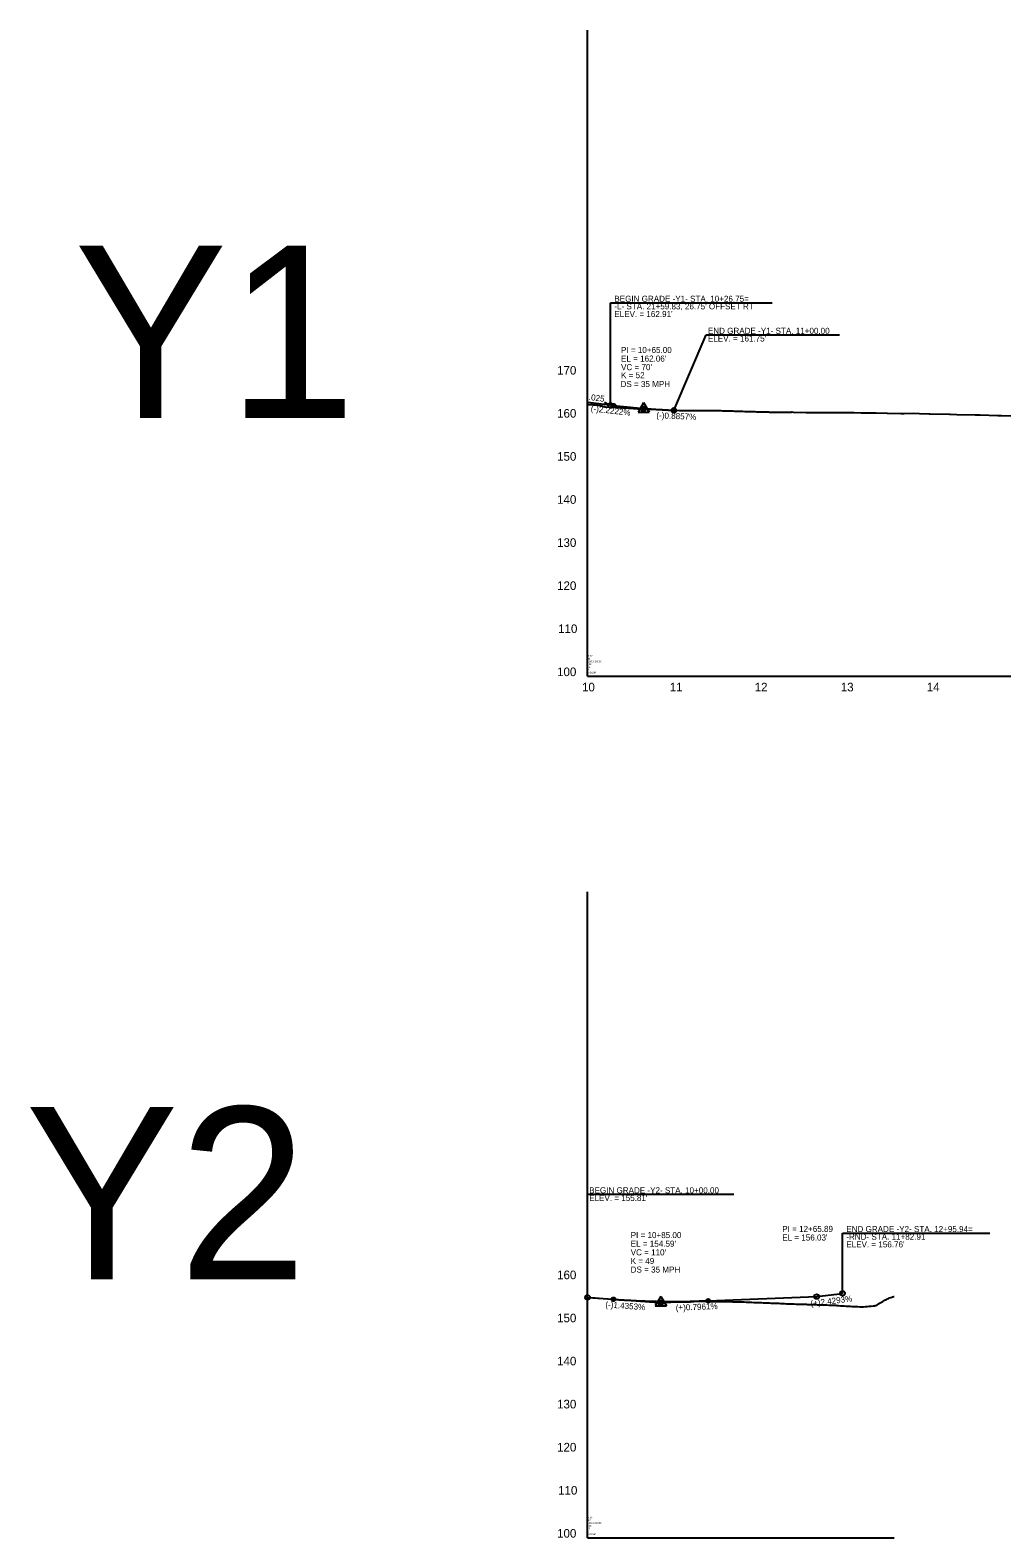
# Model space of a CAD drawing. Extents: x 1778432 to 1784301, y 601022 to 621789.
# Drawn here: x 1779496 to 1780624, y 617039 to 618789 of the extents above; entities that cross this region are included whole.
import ezdxf

# ---------------------------------------------------------------- set-up
doc = ezdxf.new("R2010")
doc.units = 0
for name, color, linetype in [('Exist Profile Cell', 7, 'Continuous'), ('Exist Vertical Profile Ground Line', 7, 'Continuous'), ('Exist Vertical Profile Horizontal Axis Label Major', 7, 'Continuous'), ('Exist Vertical Profile Vertical Axis Label', 7, 'Continuous'), ('Prop PFL Text', 7, 'Continuous'), ('Prop PFL VPI Symbol CELL', 7, 'Continuous'), ('Prop Vertical Profile Curve Label', 7, 'Continuous'), ('Prop Vertical Profile Grade', 7, 'Continuous'), ('Prop Vertical Profile Grade Label', 7, 'Continuous'), ('Prop VPI Label', 7, 'Continuous'), ('Scratch_Level_1', 7, 'Continuous')]:
    doc.layers.add(name, color=color, linetype=linetype)

msp = doc.modelspace()

# ---------------------------------------------------------------- linework, layer by layer
at = {"layer": 'Exist Profile Cell'}
for p, q in [((1780143, 618039.2), (1780143, 618789.2)), ((1780143, 618039.2), (1781686.3, 618039.2)), ((1780143, 618039.2), (1780143, 618039.2)), ((1780143, 617039.2), (1780143, 617789.2)), ((1780143, 617039.2), (1780498.9, 617039.2)), ((1780143, 617039.2), (1780143, 617039.2))]:
    msp.add_line(p, q, dxfattribs=at)
at = {"layer": 'Exist Vertical Profile Ground Line'}
for points in [[(1780143, 618354.7), (1780144.8, 618354.6), (1780147.3, 618354.6), (1780148.2, 618354.5), (1780149.8, 618354.4), (1780152.3, 618354.2), (1780154.4, 618353.9), (1780154.8, 618353.8), (1780156.7, 618353.7), (1780157.3, 618353.6), (1780157.7, 618353.5), (1780158.6, 618353.3), (1780159.2, 618353.1), (1780159.8, 618353), (1780161.5, 618352.5), (1780162.3, 618352.3), (1780163.1, 618352), (1780163.9, 618351.9), (1780190.9, 618350.4), (1780191.8, 618350.3), (1780196.1, 618350.1), (1780200.9, 618349.8), (1780225.9, 618348.8), (1780231.3, 618348.4), (1780249.6, 618347.7), (1780253.9, 618347.6), (1780268, 618347.6), (1780270, 618347.6), (1780272, 618347.6), (1780274, 618347.6), (1780275.9, 618347.6), (1780277.9, 618347.6), (1780280.1, 618347.6), (1780281, 618347.6), (1780281.9, 618347.6), (1780283.8, 618347.6), (1780285.8, 618347.6), (1780287.8, 618347.6), (1780289.8, 618347.6), (1780291.7, 618347.6), (1780292.2, 618347.6), (1780293.7, 618347.6), (1780295.7, 618347.6), (1780297.7, 618347.6), (1780299.6, 618347.5), (1780301.8, 618347.5), (1780303.6, 618347.5), (1780305.5, 618347.4), (1780307.5, 618347.3), (1780309.5, 618347.2), (1780311.5, 618347.2), (1780313.4, 618347.1), (1780315.4, 618347), (1780317.4, 618347), (1780319.4, 618346.9), (1780321.3, 618346.8), (1780323.3, 618346.8), (1780325.3, 618346.7), (1780327.3, 618346.7), (1780329.5, 618346.6), (1780331.2, 618346.6), (1780331.8, 618346.5), (1780333.2, 618346.5), (1780335.2, 618346.4), (1780337.2, 618346.4), (1780339.1, 618346.3), (1780341.1, 618346.3), (1780343, 618346.2), (1780345, 618346.2), (1780347, 618346.1), (1780349, 618346.1), (1780350.9, 618346), (1780352.9, 618346), (1780354, 618345.9), (1780354.4, 618345.9), (1780354.9, 618345.9), (1780356.9, 618345.9), (1780358.8, 618345.9), (1780360.8, 618345.9), (1780362.8, 618345.8), (1780364.8, 618345.8), (1780366.7, 618345.8), (1780368.7, 618345.8), (1780369.3, 618345.8), (1780370.7, 618345.7), (1780372.7, 618345.7), (1780373, 618345.7), (1780374.6, 618345.7), (1780376.6, 618345.7), (1780378.2, 618345.6), (1780379.3, 618345.9), (1780380, 618346), (1780381.4, 618345.6), (1780381.9, 618345.6), (1780396.7, 618345.5), (1780397.7, 618345.5), (1780401.4, 618345.5), (1780410.7, 618345.4), (1780416.1, 618345.4), (1780417.5, 618345.4), (1780418.1, 618345.4)], [(1780418.1, 618345.4), (1780432, 618345.4), (1780432.5, 618345.4), (1780433.7, 618345.4), (1780452.3, 618345.3), (1780460.6, 618345.1), (1780463.7, 618345.1), (1780467.1, 618345.1), (1780478, 618344.9), (1780490.5, 618344.8), (1780491, 618344.8), (1780506.4, 618344.4), (1780509.6, 618344.4), (1780510.4, 618344.4), (1780521.1, 618344.5), (1780528.3, 618344.4), (1780539.3, 618343.8), (1780540.7, 618343.7), (1780562.8, 618343.3), (1780563.8, 618343.3), (1780571.6, 618343.1), (1780592.6, 618342.6), (1780593.5, 618342.6), (1780598, 618342.5), (1780598.5, 618342.5), (1780619, 618342.1), (1780619.7, 618342.1), (1780623.1, 618342), (1780642, 618341.6)], [(1780143, 617318.2), (1780151.6, 617317.6), (1780170.7, 617316.2), (1780171.1, 617316.2), (1780196.9, 617314.5), (1780197.4, 617314.5), (1780208.3, 617313.8), (1780210.5, 617313.7), (1780212.7, 617313.6), (1780215, 617313.4), (1780217.2, 617313.3), (1780219.4, 617313.1), (1780221.7, 617313), (1780223.9, 617312.9), (1780226.1, 617312.7), (1780227.2, 617312.7), (1780228.4, 617312.7), (1780230.7, 617312.8), (1780232.8, 617312.8), (1780235.1, 617312.8), (1780237.3, 617312.9), (1780239.1, 617312.9), (1780239.6, 617312.9), (1780241.8, 617313), (1780244, 617313), (1780246.3, 617313), (1780248.5, 617313.1), (1780250.7, 617313.1), (1780253, 617313.1), (1780255.2, 617313.2), (1780257.4, 617313.2), (1780259.7, 617313.2), (1780261.9, 617313.3), (1780262.4, 617313.3), (1780264.2, 617313.4), (1780266.4, 617313.6), (1780268.6, 617313.8), (1780269.5, 617313.9), (1780270.9, 617313.9), (1780273.1, 617313.8), (1780275.3, 617313.8), (1780277.6, 617313.8), (1780279.8, 617313.8), (1780282, 617313.8), (1780282.8, 617313.7), (1780284.3, 617313.7), (1780286.5, 617313.7), (1780288.7, 617313.6), (1780291, 617313.6), (1780291.6, 617313.6), (1780293.2, 617313.6), (1780295.5, 617313.5), (1780297.7, 617313.5), (1780299.9, 617313.5), (1780302.2, 617313.5), (1780304.4, 617313.4), (1780305.1, 617313.4), (1780306.6, 617313.4), (1780308.9, 617313.4), (1780311.1, 617313.3), (1780313.3, 617313.3), (1780315.6, 617313.2), (1780317.8, 617313.2), (1780320.1, 617313.1), (1780322.3, 617313.1), (1780324.5, 617313), (1780326.8, 617312.9), (1780329, 617312.8), (1780331.2, 617312.7), (1780333.5, 617312.6), (1780335.7, 617312.5), (1780337.9, 617312.4), (1780338.4, 617312.4), (1780340.2, 617312.4), (1780342.4, 617312.3), (1780344.6, 617312.2), (1780346.9, 617312.1), (1780349.1, 617312), (1780351.4, 617311.9), (1780353.6, 617311.8), (1780355.8, 617311.7), (1780358.1, 617311.6), (1780360.3, 617311.6), (1780362.5, 617311.5), (1780364.8, 617311.4), (1780367, 617311.3), (1780369.2, 617311.2), (1780370.5, 617311.2), (1780371.5, 617311.1), (1780373.7, 617311), (1780375.9, 617310.9), (1780376.5, 617310.9), (1780378.2, 617310.9), (1780380.4, 617310.8), (1780382.7, 617310.7), (1780384.9, 617310.6), (1780387.1, 617310.6), (1780389.4, 617310.5), (1780391.6, 617310.4), (1780393.8, 617310.4), (1780396.1, 617310.3), (1780397, 617310.3), (1780398.3, 617310.2), (1780400.5, 617310.1), (1780402.8, 617310), (1780405, 617310), (1780406.5, 617309.9), (1780407.3, 617309.9), (1780409.5, 617309.8), (1780411.7, 617309.7), (1780414, 617309.7), (1780416.2, 617309.6), (1780418.4, 617309.5), (1780420.7, 617309.5), (1780422.9, 617309.4), (1780425.1, 617309.3), (1780425.9, 617309.3), (1780427.4, 617309.3), (1780429.6, 617309.1), (1780431.4, 617309.1), (1780431.8, 617309), (1780434.1, 617308.8), (1780436.3, 617308.6), (1780438.6, 617308.4), (1780439.3, 617308.4), (1780440.8, 617308.3), (1780443, 617308.2), (1780445.3, 617308.1), (1780447.5, 617308), (1780449.7, 617307.9), (1780452, 617307.8), (1780454.2, 617307.7), (1780455.8, 617307.6), (1780456.4, 617307.6), (1780458.7, 617307.5), (1780460.9, 617307.4), (1780461.6, 617307.3), (1780463.1, 617307.5), (1780465.4, 617307.6), (1780467.6, 617307.8), (1780469.9, 617308), (1780472.1, 617308.2), (1780474.3, 617308.4), (1780475.1, 617308.4), (1780476.1, 617308.6), (1780476.6, 617308.7), (1780477.6, 617308.9), (1780478.9, 617309.8), (1780479.4, 617310.2), (1780479.8, 617310.4), (1780480.7, 617311), (1780481, 617311.2), (1780482.3, 617311.9), (1780483.3, 617312.5), (1780484.8, 617313.3), (1780485.5, 617313.7), (1780485.9, 617313.9), (1780487.3, 617314.6), (1780487.7, 617314.9), (1780488.6, 617315.3), (1780490, 617315.9), (1780491.1, 617316.5), (1780492.3, 617317.1), (1780493.5, 617317.6), (1780494.7, 617318.1), (1780496, 617318.5), (1780496.7, 617318.8), (1780497.2, 617319), (1780498.5, 617319.3), (1780498.9, 617319.5)], [(1780396.1, 617310.3), (1780397, 617310.3), (1780398.3, 617310.2), (1780400.5, 617310.1), (1780402.8, 617310), (1780405, 617310), (1780406.5, 617309.9), (1780407.3, 617309.9), (1780409.5, 617309.8), (1780411.7, 617309.7), (1780414, 617309.7), (1780416.2, 617309.6), (1780418.4, 617309.5), (1780420.7, 617309.5), (1780422.9, 617309.4), (1780425.1, 617309.3), (1780425.9, 617309.3), (1780427.4, 617309.3), (1780429.6, 617309.1), (1780431.4, 617309.1), (1780431.8, 617309), (1780434.1, 617308.8), (1780436.3, 617308.6), (1780438.6, 617308.4), (1780439.3, 617308.4), (1780440.8, 617308.3), (1780443, 617308.2), (1780445.3, 617308.1), (1780447.5, 617308), (1780449.7, 617307.9), (1780452, 617307.8), (1780454.2, 617307.7), (1780455.8, 617307.6), (1780456.4, 617307.6), (1780458.7, 617307.5), (1780460.9, 617307.4), (1780461.6, 617307.3), (1780463.1, 617307.5), (1780465.4, 617307.6), (1780467.6, 617307.8), (1780469.9, 617308), (1780472.1, 617308.2), (1780474.3, 617308.4), (1780475.1, 617308.4), (1780476.1, 617308.6), (1780476.6, 617308.7), (1780477.6, 617308.9), (1780478.9, 617309.8), (1780479.4, 617310.2), (1780479.8, 617310.4), (1780480.7, 617311), (1780481, 617311.2), (1780482.3, 617311.9), (1780483.3, 617312.5), (1780484.8, 617313.3), (1780485.5, 617313.7), (1780485.9, 617313.9), (1780487.3, 617314.6), (1780487.7, 617314.9), (1780488.6, 617315.3), (1780490, 617315.9), (1780491.1, 617316.5), (1780492.3, 617317.1), (1780493.5, 617317.6), (1780494.7, 617318.1), (1780496, 617318.5), (1780496.7, 617318.8), (1780497.2, 617319), (1780498.5, 617319.3), (1780498.9, 617319.5)]]:
    msp.add_lwpolyline(points, dxfattribs=at)
at = {"layer": 'Prop PFL VPI Symbol CELL'}
for p, q in [((1780208, 618357), (1780201.5, 618345.8)), ((1780201.5, 618345.8), (1780214.5, 618345.8)), ((1780208, 618357), (1780214.5, 618345.8)), ((1780227.9, 617319.5), (1780221.5, 617308.3)), ((1780227.9, 617319.5), (1780234.4, 617308.3)), ((1780221.5, 617308.3), (1780234.4, 617308.3))]:
    msp.add_line(p, q, dxfattribs=at)
for centre, radius in [((1780208, 618349.5), 1.75), ((1780208, 618349.5), 1.2), ((1780227.9, 617312), 1.75), ((1780227.9, 617312), 1.2)]:
    msp.add_circle(centre, radius, dxfattribs=at)
at = {"layer": 'Prop Vertical Profile Curve Label'}
for centre in [(1780173, 618353.4), (1780243, 618347.9), (1780173, 617316.1), (1780283, 617314.3)]:
    msp.add_circle(centre, 2.25, dxfattribs=at)
at = {"layer": 'Prop Vertical Profile Grade'}
for p, q in [((1780169.7, 618353.7), (1780173, 618353.4)), ((1780143, 617318.2), (1780173, 617316.1)), ((1780283, 617314.3), (1780408.8, 617319.3)), ((1780408.8, 617319.3), (1780438.9, 617323))]:
    msp.add_line(p, q, dxfattribs=at)
for points in [[(1780173, 618353.4), (1780174.4, 618353.2), (1780175.8, 618353.1), (1780177.2, 618352.9), (1780178.6, 618352.8), (1780180, 618352.6), (1780181.4, 618352.5), (1780182.8, 618352.3), (1780184.2, 618352.2), (1780185.6, 618352.1), (1780187, 618351.9), (1780188.4, 618351.8), (1780189.8, 618351.6), (1780191.2, 618351.5), (1780192.6, 618351.4), (1780194, 618351.3), (1780195.4, 618351.1), (1780196.8, 618351), (1780198.2, 618350.9), (1780199.6, 618350.8), (1780201, 618350.6), (1780202.4, 618350.5), (1780203.8, 618350.4), (1780205.2, 618350.3), (1780206.6, 618350.2), (1780208, 618350.1), (1780209.4, 618350), (1780210.8, 618349.9), (1780212.2, 618349.8), (1780213.6, 618349.7), (1780215, 618349.6), (1780216.4, 618349.5), (1780217.8, 618349.4), (1780219.2, 618349.3), (1780220.6, 618349.2), (1780222, 618349.1), (1780223.4, 618349), (1780224.8, 618348.9), (1780226.2, 618348.8), (1780227.6, 618348.7), (1780229, 618348.7), (1780230.4, 618348.6), (1780231.8, 618348.5), (1780233.2, 618348.4), (1780234.6, 618348.3), (1780236, 618348.3), (1780237.4, 618348.2), (1780238.8, 618348.1), (1780240.2, 618348.1), (1780241.6, 618348), (1780243, 618347.9)], [(1780173, 617316.1), (1780175.2, 617315.9), (1780177.4, 617315.8), (1780179.6, 617315.6), (1780181.8, 617315.5), (1780184, 617315.4), (1780186.2, 617315.2), (1780188.4, 617315.1), (1780190.6, 617315), (1780192.8, 617314.9), (1780195, 617314.7), (1780197.2, 617314.6), (1780199.4, 617314.5), (1780201.6, 617314.4), (1780203.8, 617314.3), (1780206, 617314.3), (1780208.2, 617314.2), (1780210.4, 617314.1), (1780212.6, 617314), (1780214.8, 617314), (1780217, 617313.9), (1780219.2, 617313.8), (1780221.4, 617313.8), (1780223.6, 617313.7), (1780225.8, 617313.7), (1780228, 617313.7), (1780230.2, 617313.6), (1780232.4, 617313.6), (1780234.6, 617313.6), (1780236.8, 617313.6), (1780239, 617313.5), (1780241.2, 617313.5), (1780243.4, 617313.5), (1780245.6, 617313.5), (1780247.8, 617313.5), (1780250, 617313.6), (1780252.2, 617313.6), (1780254.4, 617313.6), (1780256.6, 617313.6), (1780258.8, 617313.6), (1780261, 617313.7), (1780263.2, 617313.7), (1780265.4, 617313.8), (1780267.6, 617313.8), (1780269.8, 617313.9), (1780272, 617313.9), (1780274.2, 617314), (1780276.4, 617314.1), (1780278.6, 617314.1), (1780280.8, 617314.2), (1780283, 617314.3)]]:
    msp.add_spline(points, degree=3, dxfattribs=at)
at = {"layer": 'Prop VPI Label'}
for p, q in [((1780169.7, 618353.7), (1780169.7, 618472.8)), ((1780169.7, 618472.8), (1780357.1, 618472.8)), ((1780243, 618347.9), (1780280.7, 618435.7)), ((1780280.7, 618435.7), (1780435.4, 618435.7)), ((1780168.4, 618353.9), (1780143.7, 618357)), ((1780168.4, 618353.9), (1780162.7, 618357.1)), ((1780173, 618353.4), (1780205.2, 618349.8)), ((1780243, 618347.9), (1780210.7, 618349.4)), ((1780143, 617318.2), (1780143, 617438.2)), ((1780143, 617438.2), (1780312.8, 617438.2)), ((1780438.9, 617393), (1780609.7, 617393)), ((1780438.9, 617323), (1780438.9, 617393)), ((1780173, 617316.1), (1780225.2, 617312.3)), ((1780283, 617314.3), (1780230.7, 617312.2))]:
    msp.add_line(p, q, dxfattribs=at)
for centre in [(1780169.7, 618353.7), (1780208, 618349.5), (1780243, 618347.9), (1780143, 617318.2), (1780228, 617312.1), (1780408.8, 617319.3), (1780438.9, 617323)]:
    msp.add_circle(centre, 2.75, dxfattribs=at)
at = {"layer": 'Scratch_Level_1'}
msp.add_line((1780181.2, 618374.9), (1780181.2, 618374.9), dxfattribs=at)

# ---------------------------------------------------------------- texts
at = {"layer": 'Exist Profile Cell'}
for s, p in [('Y1', (1780143, 618058.7)), ('2', (1780143, 618045.7)), ('RDY', (1780143, 618061.9)), ('1000.000000', (1780143, 618055.4)), ('100', (1780143, 618052.2)), ('10', (1780143, 618048.9)), ('NOGAP', (1780143, 618042.4)), ('Y2', (1780143, 617058.7)), ('RDY', (1780143, 617061.9)), ('1000.000000', (1780143, 617055.4)), ('100', (1780143, 617052.2)), ('10', (1780143, 617048.9)), ('2', (1780143, 617045.7)), ('NOGAP', (1780143, 617042.4))]:
    msp.add_text(s, height=2, dxfattribs=at).set_placement(p)
at = {"layer": 'Exist Vertical Profile Horizontal Axis Label Major'}
for s, p in [('10', (1780136.5, 618021.7)), ('11', (1780238.4, 618021.7)), ('12', (1780336.9, 618021.7)), ('13', (1780436.8, 618021.7)), ('14', (1780536.6, 618021.7))]:
    msp.add_text(s, height=10, dxfattribs=at).set_placement(p)
at = {"layer": 'Exist Vertical Profile Vertical Axis Label'}
for s, p in [('170', (1780107.6, 618389.4)), ('160', (1780107.6, 618339.4)), ('150', (1780107.6, 618289.4)), ('140', (1780107.6, 618239.4)), ('130', (1780107.6, 618189.4)), ('120', (1780107.6, 618139.4)), ('110', (1780108.8, 618089.4)), ('100', (1780107.6, 618039.4)), ('160', (1780107.6, 617339.4)), ('150', (1780107.6, 617289.4)), ('140', (1780107.6, 617239.4)), ('130', (1780107.6, 617189.4)), ('120', (1780107.6, 617139.4)), ('110', (1780108.8, 617089.4)), ('100', (1780107.6, 617039.4))]:
    msp.add_text(s, height=10, dxfattribs=at).set_placement(p)
at = {"layer": 'Prop PFL Text'}
for s, p in [('Y1', (1779546.9, 618339.2)), ('Y2', (1779490.2, 617339.2))]:
    msp.add_text(s, height=200, dxfattribs=at).set_placement(p)
at = {"layer": 'Prop Vertical Profile Curve Label'}
for s, p in [("VC = 70'", (1780181.8, 618394.5)), ('K = 52', (1780181.8, 618385.2)), ("VC = 110'", (1780193, 617367.1)), ('K = 49', (1780193, 617357.1)), ('DS = 35 MPH', (1780193, 617347.1))]:
    msp.add_text(s, height=7, dxfattribs=at).set_placement(p)
at = {"layer": 'Prop Vertical Profile Grade Label'}
for s, rotation, p in [('.025', 352.875, (1780144.1, 618360)), ('(-)2.2222%', 353.6598, (1780146.4, 618346.8)), ('(-)0.8857%', 357.4643, (1780222.7, 618338.8)), ('(-)1.4353%', 355.877, (1780163.4, 617306.7)), ('(+)2.4293%', 6.9461, (1780402.1, 617307.7)), ('(+)0.7961%', 2.2867, (1780245.4, 617302.8))]:
    msp.add_text(s, height=7, rotation=rotation, dxfattribs=at).set_placement(p)
at = {"layer": 'Prop VPI Label'}
for s, p in [("-L- STA. 21+59.83, 26.75' OFFSET RT", (1780174, 618465.1)), ('BEGIN GRADE -Y1- STA. 10+26.75=', (1780174, 618473.9)), ("ELEV. = 162.91'", (1780174, 618456.2)), ('END GRADE -Y1- STA. 11+00.00', (1780282.6, 618436.7)), ("ELEV. = 161.75'", (1780282.6, 618427.8)), ('PI = 10+65.00', (1780181.8, 618414.5)), ("EL = 162.06'", (1780181.8, 618404.5)), ('DS = 35 MPH', (1780181.2, 618374.9)), ('BEGIN GRADE -Y2- STA. 10+00.00', (1780144.8, 617439.1)), ("ELEV. = 155.81'", (1780144.8, 617430.2)), ('PI = 12+65.89', (1780368.9, 617394.3)), ('END GRADE -Y2- STA. 12+95.94=', (1780443.2, 617394.1)), ('PI = 10+85.00', (1780193, 617387.1)), ("EL = 154.59'", (1780193, 617377.1)), ("EL = 156.03'", (1780368.9, 617384.3)), ('-RND- STA. 11+82.91', (1780443.2, 617385.2)), ("ELEV. = 156.76'", (1780443.2, 617376.3))]:
    msp.add_text(s, height=7, dxfattribs=at).set_placement(p)

doc.saveas('drawing.dxf')
